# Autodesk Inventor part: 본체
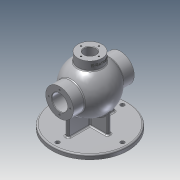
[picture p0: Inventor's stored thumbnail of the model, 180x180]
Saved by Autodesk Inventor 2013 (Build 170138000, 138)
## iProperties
Created: 2020-08
Part Number: 본체
Material: 알루미늄 6061
Document SubType Name: Modeling
Designer: user
Density: 2.71 g/cm^3
Mass: 1759.18 g
Surface Area: 1342.42 cm^2
Volume: 649.143 cm^3
Author: user
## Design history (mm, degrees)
sketch "스케치1"
  geometry: L1 (38.52, -36.403)-(-38.52, 36.403); A1 r 53 centre (0, 0) between (38.52, -36.403) and (-38.52, 36.403); 1 further point
  constraints: 2 end point, 2 point on circle, 1 centre point, 1 coincident, 1 midpoint
  dimensions: "d0" = 106 diameter of A1
revolve "회전1" sketch "스케치1" stored, may be unused: angle "d1" = 90 deg
sketch "스케치2"
  geometry: L1 (31.985, -28.74)-(-31.985, 28.74); A1 r 43 centre (0, 0) between (31.985, -28.74) and (-31.985, 28.74); 1 further point
  constraints: 2 end point, 2 point on circle, 1 centre point, 1 coincident, 1 midpoint
  dimensions: "d2" = 86 diameter of A1
revolve "회전2" sketch "스케치2" stored, may be unused: angle "d3" = 90 deg
node "작업 평면1"
sketch "스케치3"
  geometry: C1 r 31 at (0, 0); 1 further point
  constraints: 1 centre point, 1 coincident
  dimensions: "d5" = 62 diameter of C1
extrude "돌출1" join sketch "스케치3" stored distance "d6" = 10; taper "d7" = 0 deg
node "작업 평면2"
sketch "스케치7"
  geometry: C1 r 85 at (0, 0); 1 further point
  constraints: 1 centre point, 1 coincident
  dimensions: "d18" = 170 diameter of C1
extrude "돌출5" join sketch "스케치7" distance "d19" = 10; taper "d20" = 0 deg
sketch "스케치8"
  geometry: L1 (-4, 43)-(4, 43); L2 (4, 43)-(4, -43); L3 (4, -43)-(-4, -43); L4 (-4, -43)-(-4, 43); C1 r 85 at (0, 0) reference
  constraints: 8 end point, 2 parallel, 1 horizontal, 1 perpendicular
  dimensions: "d21" = 8 distance of L1.start L1.end; "d23" = 86 distance of L1.end L2.end; "d24" = 4 distance from line of C1.centre L4; "d25" = 43 distance from line of C1.centre L1
extrude "돌출6" join sketch "스케치8" stored distance "d26" = 10; taper "d27" = 0 deg
sketch "스케치9"
  geometry: L1 (-52, 4)-(52, 4); L2 (52, 4)-(52, -4); L3 (52, -4)-(-52, -4); L4 (-52, -4)-(-52, 4); C1 r 85 at (0, 0) reference
  constraints: 8 end point, 2 parallel, 1 horizontal, 1 perpendicular
  dimensions: "d28" = 8 distance of L1.end L2.end; "d30" = 104 distance of L2.end L3.end; "d31" = 4 distance from line of C1.centre L1; "d32" = 52 distance from line of C1.centre L2
extrude "돌출7" join sketch "스케치9" stored distance "d33" = 10; taper "d34" = 0 deg
node "작업 평면3"
sketch "스케치10"
  geometry: C1 r 27 at (0, 0); 1 further point
  constraints: 1 centre point, 1 coincident
  dimensions: "d36" = 54 diameter of C1
extrude "돌출8" join sketch "스케치10" stored distance "d37" = 10; taper "d38" = 0 deg
sketch "스케치11"
  geometry: C1 r 27 at (0, 0) reference; C2 r 13 at (0, 0)
  constraints: 1 centre point, 1 coincident
  dimensions: "d39" = 26 diameter of C2
extrude "돌출9" cut sketch "스케치11" distance "d40" = 100; taper "d41" = 0 deg
sketch "스케치14" dims "d49" = 145
  geometry: C1 r 85 at (0, 0) reference; 2 further points
  constraints: 2 vertical alignment, 1 coincident, 2 other
hole "구멍1" sketch "스케치14" at (0, 72.5) diameter "d50" = 9; stored, may be unused: countersink angle "d54" = 90 deg, drill point angle "d56" = 118 deg; dims "d51" = 6, "d52" = 4, "d53" = 2, "d55" = 8
sketch "스케치16" dims "d71" = 40
  geometry: C1 r 13 at (0, 0) reference; C2 r 27 at (0, 0) reference; 2 further points
  constraints: 2 vertical alignment, 1 coincident, 2 other
hole "구멍3" sketch "스케치16" at (0, 20) diameter "d72" = 3.242; stored, may be unused: countersink angle "d76" = 90 deg, drill point angle "d78" = 118 deg; dims "d73" = 12, "d74" = 4, "d75" = 2, "d77" = 15
node "작업 평면4"
sketch "스케치18"
  geometry: L1 (-27, 65)-(27, 65) reference; 3 further points
  constraints: 1 midpoint, 1 vertical alignment, 1 other
  dimensions: "d94" = 9 distance from line of point (0, 56) L1
feature "엠보싱1" sketch "스케치18" dims "d0" = 106, "d18" = 170, "d95" = 0.5, "d96" = 0
fillet "모깎기1" dims "d97" = 3
fillet "모깎기2" dims "d98" = 3
fillet "모깎기3" dims "d99" = 3
fillet "모깎기4" dims "d100" = 3
fillet "모깎기5" dims "d101" = 3
chamfer "모따기1" distance "d102" = 1; stored, may be unused: second distance "d103" = 2, angle "d104" = 45 deg
sketch "스케치19"
  geometry: C1 r 31 at (0, 0) reference; C2 r 17.5 at (0, 0)
  constraints: 1 centre point, 1 coincident
  dimensions: "d105" = 35 diameter of C2
extrude "돌출12" cut sketch "스케치19" distance "d106" = 16; taper "d107" = 0 deg
sketch "스케치20"
  geometry: C1 r 17.5 at (0, 0) reference; C2 r 18.5 at (0, 0)
  constraints: 1 centre point, 1 coincident
  dimensions: "d108" = 37 diameter of C2
extrude "돌출13" cut sketch "스케치20" distance "d109" = 1.75; taper "d110" = 0 deg
sketch "스케치21"
  geometry: C1 r 18.5 at (0, 0) reference; C2 r 17.5 at (0, 0)
  constraints: 1 centre point, 1 coincident
  dimensions: "d111" = 35 diameter of C2
extrude "돌출14" cut sketch "스케치21" stored distance "d112" = 1.75; taper "d113" = 0 deg
sketch "스케치22" dims "d114" = 48
  geometry: C1 r 17.5 at (0, 0) reference; C2 r 31 at (0, 0) reference; 2 further points
  constraints: 2 vertical alignment, 1 coincident, 2 other
hole "구멍5" sketch "스케치22" at (0, 24) diameter "d115" = 3.242; stored, may be unused: countersink angle "d119" = 90 deg, drill point angle "d121" = 118 deg; dims "d116" = 12, "d117" = 4, "d118" = 2, "d120" = 15
chamfer "모따기2" distance "d125" = 1; stored, may be unused: second distance "d126" = 2, angle "d127" = 45 deg
node "솔리드1"
mirror "대칭1"
pattern_circular "원형 패턴1" dims angle "d58" = 360 deg
pattern_circular "원형 패턴3" dims angle "d80" = 360 deg
pattern_circular "원형 패턴5" dims angle "d123" = 360 deg
mirror "대칭3"
other parameters: "d4" = 68, "d17" = -85, "d35" = 65, "d93" = 29
